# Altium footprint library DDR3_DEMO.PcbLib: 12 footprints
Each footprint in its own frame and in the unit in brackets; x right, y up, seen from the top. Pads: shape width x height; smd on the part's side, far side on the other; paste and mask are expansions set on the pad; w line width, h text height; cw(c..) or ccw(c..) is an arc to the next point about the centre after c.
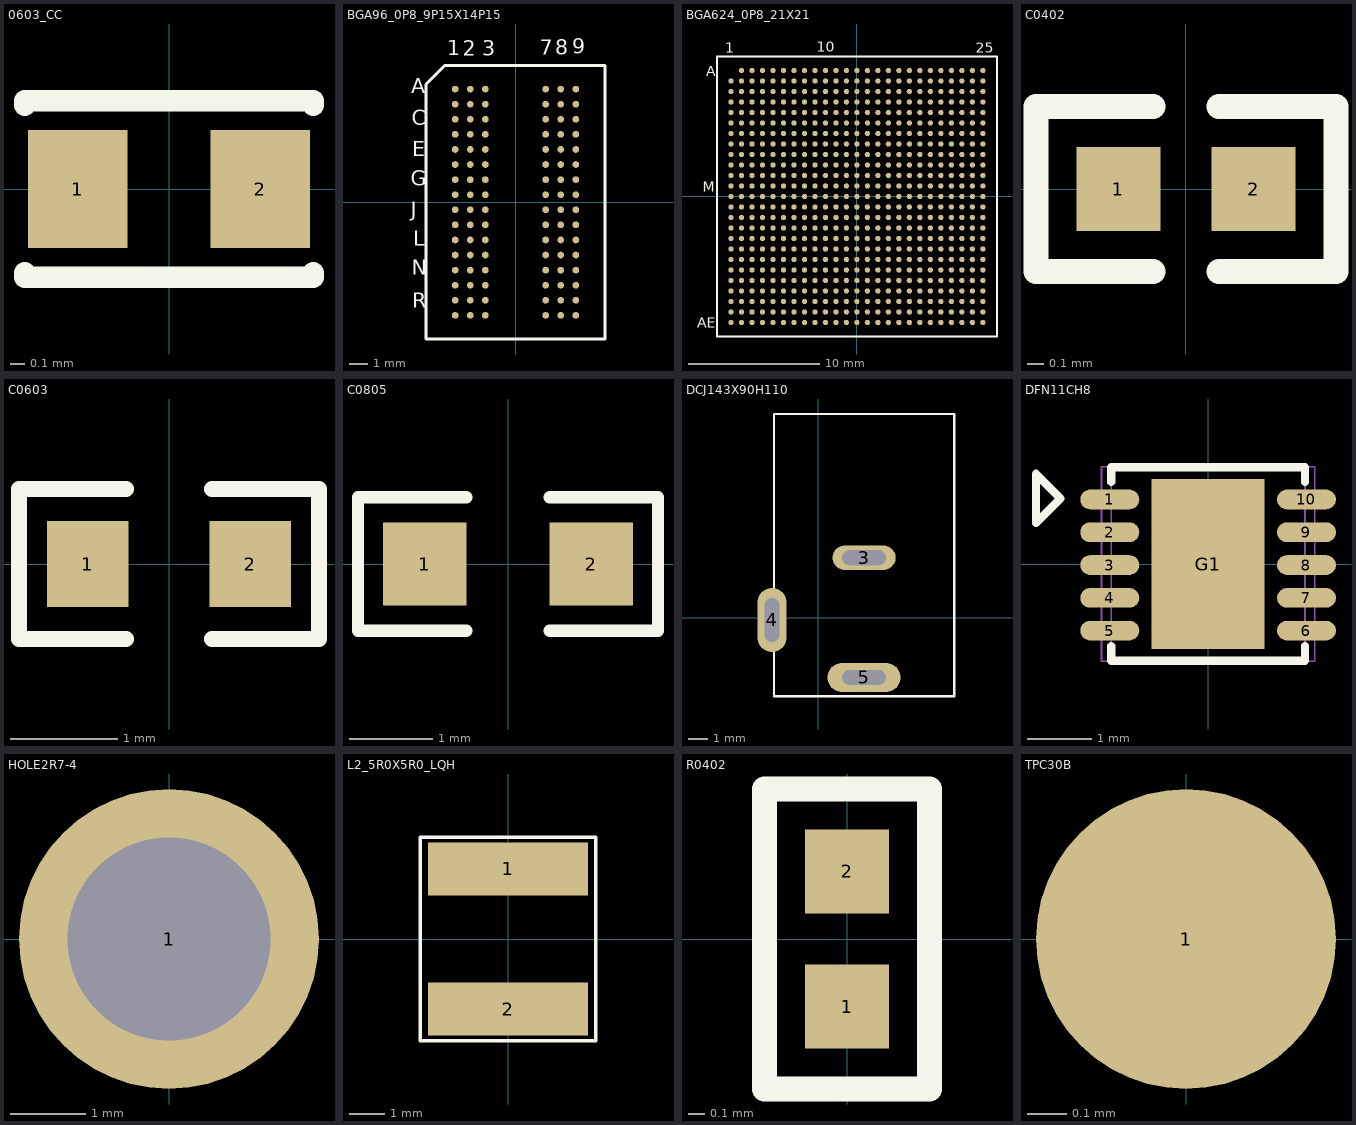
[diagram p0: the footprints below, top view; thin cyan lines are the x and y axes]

## 0603_CC [mil] "0603_CC"
pads (2):
  rect 28x33 smd: 1(-25.59,0) 2(25.59,0)
Top Overlay:
  lines w6: -40.47,-23.54 -40.47,-24.72 40.47,-24.72 40.47,-23.54 ; -40.47,23.54 -40.47,24.72 40.47,24.72 40.47,23.54

## BGA96_0P8_9P15X14P15 [mil] "BGA96_0P8_9P15X14P15"
pads (96):
  round 14 smd: A1(-125.98,236.22) A2(-94.49,236.22) A3(-62.99,236.22) A7(62.99,236.22) A8(94.49,236.22) A9(125.98,236.22) B1(-125.98,204.72) B2(-94.49,204.72) B3(-62.99,204.72) B7(62.99,204.72) B8(94.49,204.72) B9(125.98,204.72) C1(-125.98,173.23) C2(-94.49,173.23) C3(-62.99,173.23) C7(62.99,173.23) C8(94.49,173.23) C9(125.98,173.23) D1(-125.98,141.73) D2(-94.49,141.73) D3(-62.99,141.73) D7(62.99,141.73) D8(94.49,141.73) D9(125.98,141.73) E1(-125.98,110.24) E2(-94.49,110.24) E3(-62.99,110.24) E7(62.99,110.24) E8(94.49,110.24) E9(125.98,110.24) F1(-125.98,78.74) F2(-94.49,78.74) F3(-62.99,78.74) F7(62.99,78.74) F8(94.49,78.74) F9(125.98,78.74) G1(-125.98,47.24) G2(-94.49,47.24) G3(-62.99,47.24) G7(62.99,47.24) G8(94.49,47.24) G9(125.98,47.24) H1(-125.98,15.75) H2(-94.49,15.75) H3(-62.99,15.75) H7(62.99,15.75) H8(94.49,15.75) H9(125.98,15.75) J1(-125.98,-15.75) J2(-94.49,-15.75) J3(-62.99,-15.75) J7(62.99,-15.75) J8(94.49,-15.75) J9(125.98,-15.75) K1(-125.98,-47.24) K2(-94.49,-47.24) K3(-62.99,-47.24) K7(62.99,-47.24) K8(94.49,-47.24) K9(125.98,-47.24) L1(-125.98,-78.74) L2(-94.49,-78.74) L3(-62.99,-78.74) L7(62.99,-78.74) L8(94.49,-78.74) L9(125.98,-78.74) M1(-125.98,-110.24) M2(-94.49,-110.24) M3(-62.99,-110.24) M7(62.99,-110.24) M8(94.49,-110.24) M9(125.98,-110.24) N1(-125.98,-141.73) N2(-94.49,-141.73) N3(-62.99,-141.73) N7(62.99,-141.73) N8(94.49,-141.73) N9(125.98,-141.73) P1(-125.98,-173.23) P2(-94.49,-173.23) P3(-62.99,-173.23) P7(62.99,-173.23) P8(94.49,-173.23) P9(125.98,-173.23) R1(-125.98,-204.72) R2(-94.49,-204.72) R3(-62.99,-204.72) R7(62.99,-204.72) R8(94.49,-204.72) R9(125.98,-204.72) T1(-125.98,-236.22) T2(-94.49,-236.22) T3(-62.99,-236.22) T7(62.99,-236.22) T8(94.49,-236.22) T9(125.98,-236.22)
Top Overlay:
  lines w6: -187.12,-285.54 187.12,-285.54 187.12,285.54 -147.76,285.54 -187.12,246.18 -187.12,-285.55
  text "A" at -217.68,227.56 h31
  text "1" at -142.09,306.69 h31
  text "9" at 118.15,309.84 h31
  text "3" at -69.65,306.3 h31
  text "7" at 50.83,307.87 h31
  text "C" at -216.5,160.63 h31
  text "E" at -215.31,96.06 h31
  text "G" at -218.46,34.25 h31
  text "J" at -218.46,-30.31 h31
  text "L" at -213.74,-90.55 h31
  text "N" at -216.5,-151.18 h31
  text "R" at -216.1,-220.08 h31
  text "2" at -109.8,306.3 h31
  text "8" at 83.11,307.87 h31

## BGA624_0P8_21X21 [mil] "BGA624_0P8_21X21"
pads (624):
  round 16 smd: A2(-346.46,377.95) A3(-314.96,377.95) A4(-283.46,377.95) A5(-251.97,377.95) A6(-220.47,377.95) A7(-188.98,377.95) A8(-157.48,377.95) A9(-125.98,377.95) A10(-94.49,377.95) A11(-62.99,377.95) A12(-31.5,377.95) A13(0,377.95) A14(31.5,377.95) A15(62.99,377.95) A16(94.49,377.95) A17(125.98,377.95) A18(157.48,377.95) A19(188.98,377.95) A20(220.47,377.95) A21(251.97,377.95) A22(283.46,377.95) A23(314.96,377.95) A24(346.46,377.95) A25(377.95,377.95) AA1(-377.95,-251.97) AA2(-346.46,-251.97) AA3(-314.96,-251.97) AA4(-283.46,-251.97) AA5(-251.97,-251.97) AA6(-220.47,-251.97) AA7(-188.98,-251.97) AA8(-157.48,-251.97) AA9(-125.98,-251.97) AA10(-94.49,-251.97) AA11(-62.99,-251.97) AA12(-31.5,-251.97) AA13(0,-251.97) AA14(31.5,-251.97) AA15(62.99,-251.97) AA16(94.49,-251.97) AA17(125.98,-251.97) AA18(157.48,-251.97) AA19(188.98,-251.97) AA20(220.47,-251.97) AA21(251.97,-251.97) AA22(283.46,-251.97) AA23(314.96,-251.97) AA24(346.46,-251.97) AA25(377.95,-251.97) AB1(-377.95,-283.46) AB2(-346.46,-283.46) AB3(-314.96,-283.46) AB4(-283.46,-283.46) AB5(-251.97,-283.46) AB6(-220.47,-283.46) AB7(-188.98,-283.46) AB8(-157.48,-283.46) AB9(-125.98,-283.46) AB10(-94.49,-283.46) AB11(-62.99,-283.46) AB12(-31.5,-283.46) AB13(0,-283.46) AB14(31.5,-283.46) AB15(62.99,-283.46) AB16(94.49,-283.46) AB17(125.98,-283.46) AB18(157.48,-283.46) AB19(188.98,-283.46) AB20(220.47,-283.46) AB21(251.97,-283.46) AB22(283.46,-283.46) AB23(314.96,-283.46) AB24(346.46,-283.46) AB25(377.95,-283.46) AC1(-377.95,-314.96) AC2(-346.46,-314.96) AC3(-314.96,-314.96) AC4(-283.46,-314.96) AC5(-251.97,-314.96) AC6(-220.47,-314.96) AC7(-188.98,-314.96) AC8(-157.48,-314.96) AC9(-125.98,-314.96) AC10(-94.49,-314.96) AC11(-62.99,-314.96) AC12(-31.5,-314.96) AC13(0,-314.96) AC14(31.5,-314.96) AC15(62.99,-314.96) AC16(94.49,-314.96) AC17(125.98,-314.96) AC18(157.48,-314.96) AC19(188.98,-314.96) AC20(220.47,-314.96) AC21(251.97,-314.96) AC22(283.46,-314.96) AC23(314.96,-314.96) AC24(346.46,-314.96) AC25(377.95,-314.96) AD1(-377.95,-346.46) AD2(-346.46,-346.46) AD3(-314.96,-346.46) AD4(-283.46,-346.46) AD5(-251.97,-346.46) AD6(-220.47,-346.46) AD7(-188.98,-346.46) AD8(-157.48,-346.46) AD9(-125.98,-346.46) AD10(-94.49,-346.46) AD11(-62.99,-346.46) AD12(-31.5,-346.46) AD13(0,-346.46) AD14(31.5,-346.46) AD15(62.99,-346.46) AD16(94.49,-346.46) AD17(125.98,-346.46) AD18(157.48,-346.46) AD19(188.98,-346.46) AD20(220.47,-346.46) AD21(251.97,-346.46) AD22(283.46,-346.46) AD23(314.96,-346.46) AD24(346.46,-346.46) AD25(377.95,-346.46) AE1(-377.95,-377.95) AE2(-346.46,-377.95) AE3(-314.96,-377.95) AE4(-283.46,-377.95) AE5(-251.97,-377.95) AE6(-220.47,-377.95) AE7(-188.98,-377.95) AE8(-157.48,-377.95) AE9(-125.98,-377.95) AE10(-94.49,-377.95) AE11(-62.99,-377.95) AE12(-31.5,-377.95) AE13(0,-377.95) AE14(31.5,-377.95) AE15(62.99,-377.95) AE16(94.49,-377.95) AE17(125.98,-377.95) AE18(157.48,-377.95) AE19(188.98,-377.95) AE20(220.47,-377.95) AE21(251.97,-377.95) AE22(283.46,-377.95) AE23(314.96,-377.95) AE24(346.46,-377.95) AE25(377.95,-377.95) B1(-377.95,346.46) B2(-346.46,346.46) B3(-314.96,346.46) B4(-283.46,346.46) B5(-251.97,346.46) B6(-220.47,346.46) B7(-188.98,346.46) B8(-157.48,346.46) B9(-125.98,346.46) B10(-94.49,346.46) B11(-62.99,346.46) B12(-31.5,346.46) B13(0,346.46) B14(31.5,346.46) B15(62.99,346.46) B16(94.49,346.46) B17(125.98,346.46) B18(157.48,346.46) B19(188.98,346.46) B20(220.47,346.46) B21(251.97,346.46) B22(283.46,346.46) B23(314.96,346.46) B24(346.46,346.46) B25(377.95,346.46) C1(-377.95,314.96) C2(-346.46,314.96) C3(-314.96,314.96) C4(-283.46,314.96) C5(-251.97,314.96) C6(-220.47,314.96) C7(-188.98,314.96) C8(-157.48,314.96) C9(-125.98,314.96) C10(-94.49,314.96) C11(-62.99,314.96) C12(-31.5,314.96) C13(0,314.96) C14(31.5,314.96) C15(62.99,314.96) C16(94.49,314.96) C17(125.98,314.96) C18(157.48,314.96) C19(188.98,314.96) C20(220.47,314.96) C21(251.97,314.96) C22(283.46,314.96) C23(314.96,314.96) C24(346.46,314.96) C25(377.95,314.96) D1(-377.95,283.46) D2(-346.46,283.46) D3(-314.96,283.46) D4(-283.46,283.46) D5(-251.97,283.46) D6(-220.47,283.46) D7(-188.98,283.46) D8(-157.48,283.46) D9(-125.98,283.46) D10(-94.49,283.46) D11(-62.99,283.46) D12(-31.5,283.46) D13(0,283.46) D14(31.5,283.46) D15(62.99,283.46) D16(94.49,283.46) D17(125.98,283.46) D18(157.48,283.46) D19(188.98,283.46) D20(220.47,283.46) D21(251.97,283.46) D22(283.46,283.46) D23(314.96,283.46) D24(346.46,283.46) D25(377.95,283.46) E1(-377.95,251.97) E2(-346.46,251.97) E3(-314.96,251.97) E4(-283.46,251.97) E5(-251.97,251.97) E6(-220.47,251.97) E7(-188.98,251.97) E8(-157.48,251.97) E9(-125.98,251.97) E10(-94.49,251.97) E11(-62.99,251.97) E12(-31.5,251.97) E13(0,251.97) E14(31.5,251.97) E15(62.99,251.97) E16(94.49,251.97) E17(125.98,251.97) E18(157.48,251.97) E19(188.98,251.97) E20(220.47,251.97) E21(251.97,251.97) E22(283.46,251.97) E23(314.96,251.97) E24(346.46,251.97) E25(377.95,251.97) F1(-377.95,220.47) F2(-346.46,220.47) F3(-314.96,220.47) F4(-283.46,220.47) F5(-251.97,220.47) F6(-220.47,220.47) F7(-188.98,220.47) F8(-157.48,220.47) F9(-125.98,220.47) F10(-94.49,220.47) F11(-62.99,220.47) F12(-31.5,220.47) F13(0,220.47) F14(31.5,220.47) F15(62.99,220.47) F16(94.49,220.47) F17(125.98,220.47) F18(157.48,220.47) F19(188.98,220.47) F20(220.47,220.47) F21(251.97,220.47) F22(283.46,220.47) F23(314.96,220.47) F24(346.46,220.47) F25(377.95,220.47) G1(-377.95,188.98) G2(-346.46,188.98) G3(-314.96,188.98) G4(-283.46,188.98) G5(-251.97,188.98) G6(-220.47,188.98) G7(-188.98,188.98) G8(-157.48,188.98) G9(-125.98,188.98) G10(-94.49,188.98) G11(-62.99,188.98) G12(-31.5,188.98) G13(0,188.98) G14(31.5,188.98) G15(62.99,188.98) G16(94.49,188.98) G17(125.98,188.98) G18(157.48,188.98) G19(188.98,188.98) G20(220.47,188.98) G21(251.97,188.98) G22(283.46,188.98) G23(314.96,188.98) G24(346.46,188.98) G25(377.95,188.98) H1(-377.95,157.48) H2(-346.46,157.48) H3(-314.96,157.48) H4(-283.46,157.48) H5(-251.97,157.48) H6(-220.47,157.48) H7(-188.98,157.48) H8(-157.48,157.48) H9(-125.98,157.48) H10(-94.49,157.48) H11(-62.99,157.48) H12(-31.5,157.48) H13(0,157.48) H14(31.5,157.48) H15(62.99,157.48) H16(94.49,157.48) H17(125.98,157.48) H18(157.48,157.48) H19(188.98,157.48) H20(220.47,157.48) H21(251.97,157.48) H22(283.46,157.48) H23(314.96,157.48) H24(346.46,157.48) H25(377.95,157.48) J1(-377.95,125.98) J2(-346.46,125.98) J3(-314.96,125.98) J4(-283.46,125.98) J5(-251.97,125.98) J6(-220.47,125.98) J7(-188.98,125.98) J8(-157.48,125.98) J9(-125.98,125.98) J10(-94.49,125.98) J11(-62.99,125.98) J12(-31.5,125.98) J13(0,125.98) J14(31.5,125.98) J15(62.99,125.98) J16(94.49,125.98) J17(125.98,125.98) J18(157.48,125.98) J19(188.98,125.98) J20(220.47,125.98) J21(251.97,125.98) J22(283.46,125.98) J23(314.96,125.98) J24(346.46,125.98) J25(377.95,125.98) K1(-377.95,94.49) K2(-346.46,94.49) K3(-314.96,94.49) K4(-283.46,94.49) K5(-251.97,94.49) K6(-220.47,94.49) K7(-188.98,94.49) K8(-157.48,94.49) K9(-125.98,94.49) K10(-94.49,94.49) K11(-62.99,94.49) K12(-31.5,94.49) K13(0,94.49) K14(31.5,94.49) K15(62.99,94.49) K16(94.49,94.49) K17(125.98,94.49) K18(157.48,94.49) K19(188.98,94.49) K20(220.47,94.49) K21(251.97,94.49) K22(283.46,94.49) K23(314.96,94.49) K24(346.46,94.49) K25(377.95,94.49) L1(-377.95,62.99) L2(-346.46,62.99) L3(-314.96,62.99) L4(-283.46,62.99) L5(-251.97,62.99) L6(-220.47,62.99) L7(-188.98,62.99) L8(-157.48,62.99) L9(-125.98,62.99) L10(-94.49,62.99) L11(-62.99,62.99) L12(-31.5,62.99) L13(0,62.99) L14(31.5,62.99) L15(62.99,62.99) L16(94.49,62.99) L17(125.98,62.99) L18(157.48,62.99) L19(188.98,62.99) L20(220.47,62.99) L21(251.97,62.99) L22(283.46,62.99) L23(314.96,62.99) L24(346.46,62.99) L25(377.95,62.99) M1(-377.95,31.5) M2(-346.46,31.5) M3(-314.96,31.5) M4(-283.46,31.5) M5(-251.97,31.5) M6(-220.47,31.5) M7(-188.98,31.5) M8(-157.48,31.5) M9(-125.98,31.5) M10(-94.49,31.5) M11(-62.99,31.5) M12(-31.5,31.5) M13(0,31.5) M14(31.5,31.5) M15(62.99,31.5) M16(94.49,31.5) M17(125.98,31.5) M18(157.48,31.5) M19(188.98,31.5) M20(220.47,31.5) M21(251.97,31.5) M22(283.46,31.5) M23(314.96,31.5) M24(346.46,31.5) M25(377.95,31.5) N1(-377.95,0) N2(-346.46,0) N3(-314.96,0) N4(-283.46,0) N5(-251.97,0) N6(-220.47,0) N7(-188.98,0) N8(-157.48,0) N9(-125.98,0) N10(-94.49,0) N11(-62.99,0) N12(-31.5,0) N13(0,0) N14(31.5,0) N15(62.99,0) N16(94.49,0) N17(125.98,0) N18(157.48,0) N19(188.98,0) N20(220.47,0) N21(251.97,0) N22(283.46,0) N23(314.96,0) N24(346.46,0) N25(377.95,0) P1(-377.95,-31.5) P2(-346.46,-31.5) P3(-314.96,-31.5) P4(-283.46,-31.5) P5(-251.97,-31.5) P6(-220.47,-31.5) P7(-188.98,-31.5) P8(-157.48,-31.5) P9(-125.98,-31.5) P10(-94.49,-31.5) P11(-62.99,-31.5) P12(-31.5,-31.5) P13(0,-31.5) P14(31.5,-31.5) P15(62.99,-31.5) P16(94.49,-31.5) P17(125.98,-31.5) P18(157.48,-31.5) P19(188.98,-31.5) P20(220.47,-31.5) P21(251.97,-31.5) P22(283.46,-31.5) P23(314.96,-31.5) P24(346.46,-31.5) P25(377.95,-31.5) R1(-377.95,-62.99) R2(-346.46,-62.99) R3(-314.96,-62.99) R4(-283.46,-62.99) R5(-251.97,-62.99) R6(-220.47,-62.99) R7(-188.98,-62.99) R8(-157.48,-62.99) R9(-125.98,-62.99) R10(-94.49,-62.99) R11(-62.99,-62.99) R12(-31.5,-62.99) R13(0,-62.99) R14(31.5,-62.99) R15(62.99,-62.99) R16(94.49,-62.99) R17(125.98,-62.99) R18(157.48,-62.99) R19(188.98,-62.99) R20(220.47,-62.99) R21(251.97,-62.99) R22(283.46,-62.99) R23(314.96,-62.99) R24(346.46,-62.99) R25(377.95,-62.99) T1(-377.95,-94.49) T2(-346.46,-94.49) T3(-314.96,-94.49) T4(-283.46,-94.49) T5(-251.97,-94.49) T6(-220.47,-94.49) T7(-188.98,-94.49) T8(-157.48,-94.49) T9(-125.98,-94.49) T10(-94.49,-94.49) T11(-62.99,-94.49) T12(-31.5,-94.49) T13(0,-94.49) T14(31.5,-94.49) T15(62.99,-94.49) T16(94.49,-94.49) T17(125.98,-94.49) T18(157.48,-94.49) T19(188.98,-94.49) T20(220.47,-94.49) T21(251.97,-94.49) T22(283.46,-94.49) T23(314.96,-94.49) T24(346.46,-94.49) T25(377.95,-94.49) U1(-377.95,-125.98) U2(-346.46,-125.98) U3(-314.96,-125.98) U4(-283.46,-125.98) U5(-251.97,-125.98) U6(-220.47,-125.98) U7(-188.98,-125.98) U8(-157.48,-125.98) U9(-125.98,-125.98) U10(-94.49,-125.98) U11(-62.99,-125.98) U12(-31.5,-125.98) U13(0,-125.98) U14(31.5,-125.98) U15(62.99,-125.98) U16(94.49,-125.98) U17(125.98,-125.98) U18(157.48,-125.98) U19(188.98,-125.98) U20(220.47,-125.98) U21(251.97,-125.98) U22(283.46,-125.98) U23(314.96,-125.98) U24(346.46,-125.98) U25(377.95,-125.98) V1(-377.95,-157.48) V2(-346.46,-157.48) V3(-314.96,-157.48) V4(-283.46,-157.48) V5(-251.97,-157.48) V6(-220.47,-157.48) V7(-188.98,-157.48) V8(-157.48,-157.48) V9(-125.98,-157.48) V10(-94.49,-157.48) V11(-62.99,-157.48) V12(-31.5,-157.48) V13(0,-157.48) V14(31.5,-157.48) V15(62.99,-157.48) V16(94.49,-157.48) V17(125.98,-157.48) V18(157.48,-157.48) V19(188.98,-157.48) V20(220.47,-157.48) V21(251.97,-157.48) V22(283.46,-157.48) V23(314.96,-157.48) V24(346.46,-157.48) V25(377.95,-157.48) W1(-377.95,-188.98) W2(-346.46,-188.98) W3(-314.96,-188.98) W4(-283.46,-188.98) W5(-251.97,-188.98) W6(-220.47,-188.98) W7(-188.98,-188.98) W8(-157.48,-188.98) W9(-125.98,-188.98) W10(-94.49,-188.98) W11(-62.99,-188.98) W12(-31.5,-188.98) W13(0,-188.98) W14(31.5,-188.98) W15(62.99,-188.98) W16(94.49,-188.98) W17(125.98,-188.98) W18(157.48,-188.98) W19(188.98,-188.98) W20(220.47,-188.98) W21(251.97,-188.98) W22(283.46,-188.98) W23(314.96,-188.98) W24(346.46,-188.98) W25(377.95,-188.98) Y1(-377.95,-220.47) Y2(-346.46,-220.47) Y3(-314.96,-220.47) Y4(-283.46,-220.47) Y5(-251.97,-220.47) Y6(-220.47,-220.47) Y7(-188.98,-220.47) Y8(-157.48,-220.47) Y9(-125.98,-220.47) Y10(-94.49,-220.47) Y11(-62.99,-220.47) Y12(-31.5,-220.47) Y13(0,-220.47) Y14(31.5,-220.47) Y15(62.99,-220.47) Y16(94.49,-220.47) Y17(125.98,-220.47) Y18(157.48,-220.47) Y19(188.98,-220.47) Y20(220.47,-220.47) Y21(251.97,-220.47) Y22(283.46,-220.47) Y23(314.96,-220.47) Y24(346.46,-220.47) Y25(377.95,-220.47)
Top Overlay:
  lines w6: -420.39,-420.39 420.39,-420.39 420.39,420.39 -420.39,420.39 -420.39,-420.39
  text "AE" at -479.82,-394.63 h31
  text "A" at -452.72,360.45 h31
  text "1" at -395.56,431.56 h31
  text "25" at 356.91,431.2 h31
  text "10" at -121.16,434.23 h31
  text "M" at -462.6,13.52 h31

## C0402 [mm] "C0402"
pads (2):
  rect 0.51x0.51 smd: 1(-0.41,0) 2(0.41,0)
Top Overlay:
  lines w0.15: -0.2,-0.5 -0.91,-0.5 -0.91,0.5 -0.2,0.5 ; 0.2,-0.5 0.91,-0.5 0.91,0.5 0.2,0.5

## C0603 [mil] "C0603"
pads (2):
  rect 29.92x31.5 smd: 1(-29.92,0) 2(29.92,0)
Top Overlay:
  lines w5.91: -15.75,-27.56 -55.12,-27.56 -55.12,27.56 -15.75,27.56 ; 15.75,-27.56 55.12,-27.56 55.12,27.56 15.75,27.56

## C0805 [mm] "C0805"
pads (2):
  rect 1x1 smd: 1(-1.001,0) 2(1.001,0)
Top Overlay:
  lines w0.15: -1.699,0.8 -0.5,0.8 ; -1.6,0.8 -1.801,0.8 -1.801,-0.8 -0.5,-0.8 ; 0.5,-0.8 1.801,-0.8 1.801,0.8 0.5,0.8

## DCJ143X90H110 [mil] "DCJ143X90H110"
pads (3):
  oval 130x50 hole 30 slot 90 at 0 deg: 3(94.49,123.03)
  oval 60x132 hole 30 slot 90 at 90 deg: 4(-94.49,-4.89)
  oval 150x60 hole 30 slot 90 at 0 deg: 5(94.49,-123.03)
Top Overlay:
  lines w5: -90.51,-161.66 -90.51,418.35 279.49,418.35 279.49,-161.66 89.95,-161.66 -90.51,-161.66

## DFN11CH8 [mil] "DFN11CH8"
pads (11):
  oval 36x12 smd: 1(-59.98,39.37) 2(-59.98,19.37) 3(-59.98,-0.63) 4(-59.98,-20.64) 5(-59.98,-40.64) 6(60.02,-40.64) 7(60.02,-20.64) 8(60.02,-0.63) 9(60.02,19.37) 10(60.02,39.37)
  rect 69x104 smd: G1(0.02,0)
Top Overlay:
  lines w5: -59.04,-50 -59.04,-59.06 59.08,-59.06 59.08,-50 ; -59.04,50 -59.04,59.06 59.08,59.06 59.08,50 ; -104.98,25 -104.98,55 -89.98,40 -104.98,25
Mechanical 12:
  text "9" at 50.02,19.37 h25
  text "10" at 40.02,39.37 h25
  text "8" at 50.02,-0.63 h25
  text "5" at -69.98,-40.64 h25
  text "6" at 50.02,-40.64 h25
  text "4" at -69.98,-20.64 h25
  text "2" at -69.98,19.37 h25
  text "1" at -69.98,39.37 h25
  text "3" at -69.98,-0.63 h25
  text "G1" at -39.98,0 h25
  text "7" at 50.02,-20.64 h25
Mechanical 14:
  lines w1: -65.06,-59.37 65.06,-59.37 65.06,59.37 -65.06,59.37 -65.06,-59.37
Mechanical 15:
  lines w1: -59.04,-59.06 59.08,-59.06 59.08,59.06 -59.04,59.06 -59.04,-59.06
  text "A=0.8MM" at -84.98,-90 h25
  text ".Designator" at -64.98,90 h50
Mechanical 16:
  lines w1: -65.06,-59.37 65.06,-59.37 65.06,59.37 -65.06,59.37 -65.06,-59.37

## HOLE2R7-4 [mm] "HOLE2R7-4"
pads (1):
  round 4 / inner round 1.524 / far side round 1.524 hole 2.7: 1(0,0)
Mechanical 12:
  text "1" at -0.254,0 h0.64

## L2_5R0X5R0_LQH [mm] "L2_5R0X5R0_LQH"
pads (2):
  rect 4.57x1.52 smd: 1(0,2) 2(0,-2)
Top Overlay:
  lines w0.1: -2.5,-2.9 -2.5,2.9 2.5,2.9 2.5,-2.9 -2.5,-2.9

## R0402 [mm] "R0402"
pads (2):
  rect 0.51x0.51 smd: 1(0,-0.41) 2(0,0.41)
Top Overlay:
  lines w0.15: -0.5,-0.91 -0.5,0.91 0.5,0.91 0.5,-0.91 -0.5,-0.91

## TPC30B [mil] "TPC30B"
pads (1):
  round 30 smd: 1(0,0)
